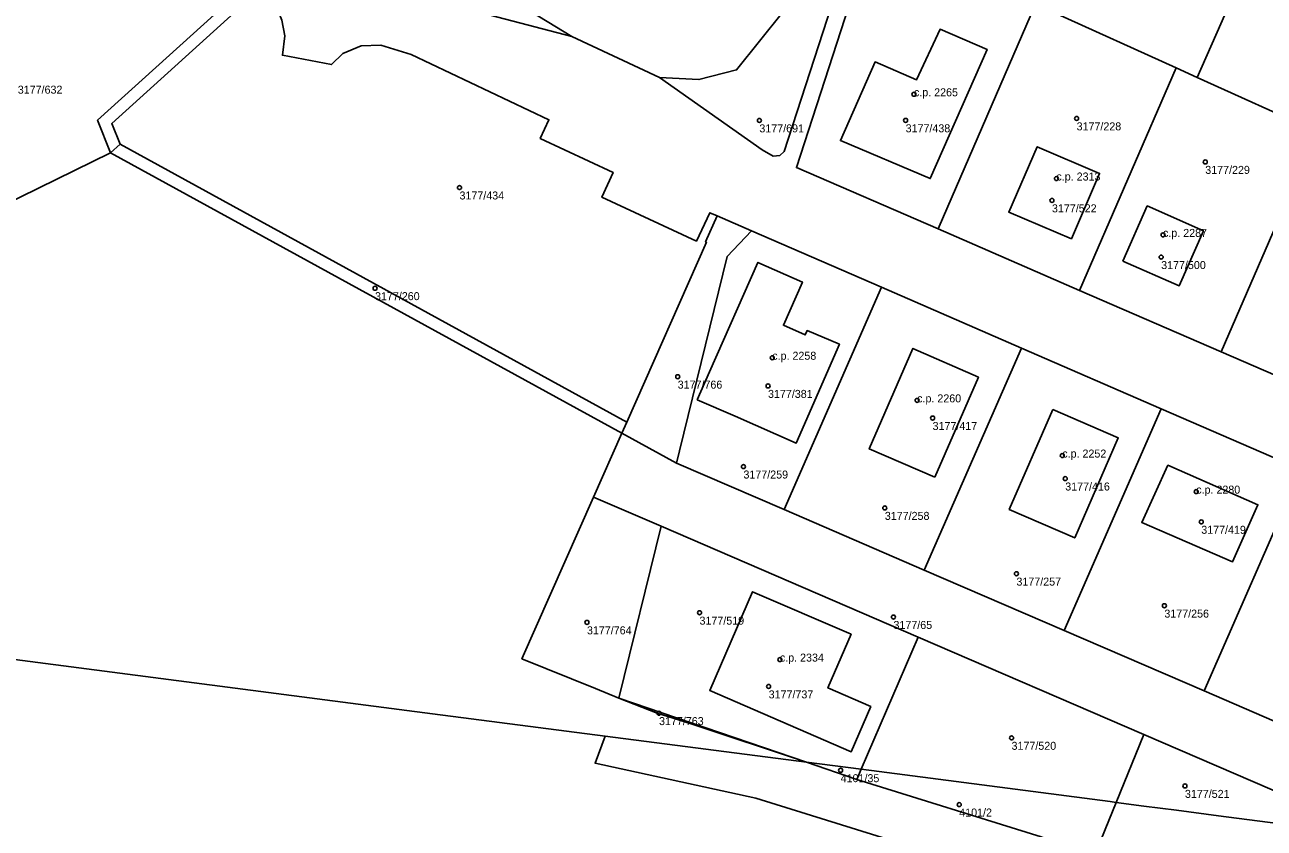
# Model space of a CAD drawing. Extents: x -878211 to -870363, y -1058464 to -1052522.
# Drawn here: x -874398.3 to -874243.4, y -1057039.9 to -1056939.4 of the extents above; entities that cross this region are included whole.
import ezdxf

# ---------------------------------------------------------------- set-up
doc = ezdxf.new("R2010")
doc.units = 0
for name, color, linetype in [('Vrstva 50', 7, 'Continuous'), ('Vrstva 51', 7, 'Continuous'), ('Vrstva 52', 7, 'Continuous')]:
    doc.layers.add(name, color=color, linetype=linetype)

msp = doc.modelspace()

# ---------------------------------------------------------------- linework, layer by layer
at = {"layer": 'Vrstva 50'}
for centre in [(-874287.13, -1056948.10994), (-874306.45, -1056951.37994), (-874288.17, -1056951.36994), (-874266.8, -1056951.12994), (-874250.72, -1056956.56994), (-874269.32, -1056958.63994), (-874343.93, -1056959.76994), (-874269.88, -1056961.37994), (-874256, -1056965.68994), (-874256.23, -1056968.46994), (-874354.49, -1056972.35994), (-874304.84, -1056981.04994), (-874316.66, -1056983.41994), (-874305.37, -1056984.57994), (-874286.73, -1056986.37994), (-874284.8, -1056988.58994), (-874268.59, -1056993.27994), (-874308.44, -1056994.65994), (-874268.22, -1056996.15994), (-874251.85, -1056997.78994), (-874290.77, -1056999.82994), (-874251.22, -1057001.56994), (-874274.32, -1057008.04994), (-874255.83, -1057012.04994), (-874313.93, -1057012.92994), (-874289.69, -1057013.46994), (-874328, -1057014.13994), (-874303.89, -1057018.78994), (-874305.29, -1057022.14994), (-874318.99, -1057025.48994), (-874274.93, -1057028.57994), (-874296.29, -1057032.62994), (-874253.26, -1057034.58994), (-874281.47, -1057036.91994)]:
    msp.add_circle(centre, 0.25, dxfattribs=at)
at = {"layer": 'Vrstva 51'}
for points in [[(-874324.96, -1056884.65), (-874320.96, -1056886.71), (-874320.59, -1056885.96), (-874317.31, -1056887.36), (-874315.74, -1056882.81), (-874317.2, -1056882.28), (-874322.56, -1056881.47), (-874325, -1056882.05), (-874327.32, -1056883.85), (-874328.98, -1056886.28), (-874331.81, -1056891.54), (-874351.14, -1056927.66), (-874351.9, -1056930.02), (-874352, -1056931.99), (-874351.54, -1056933.93), (-874344.73, -1056937.02), (-874329.9, -1056940.87), (-874340.09, -1056934.61), (-874342.8, -1056928.11), (-874342.12, -1056920.85), (-874331.98, -1056902.66), (-874326.54, -1056897.55), (-874323.49, -1056891.62), (-874327.49, -1056889.54)], [(-874323.68, -1056901.06), (-874326.54, -1056897.55), (-874331.98, -1056902.66), (-874342.12, -1056920.85), (-874342.8, -1056928.11), (-874340.09, -1056934.61), (-874329.9, -1056940.87), (-874318.93, -1056946), (-874314, -1056946.27), (-874309.3, -1056945.06), (-874300.68, -1056934.27), (-874293.26, -1056915.3), (-874296.22, -1056916.61), (-874298.98, -1056910.87)], [(-874254.36, -1056944.8), (-874251.74, -1056945.99), (-874239.29, -1056917.7), (-874257.28, -1056909.78), (-874269.65, -1056937.89)], [(-874303.34, -1056955.27), (-874289.89, -1056913.8), (-874293.26, -1056915.3), (-874300.68, -1056934.27), (-874309.3, -1056945.06), (-874314, -1056946.27), (-874318.93, -1056946), (-874306.08, -1056955.04), (-874304.71, -1056955.83), (-874303.88, -1056955.75)], [(-874233.82, -1056954.08), (-874230.38, -1056946.25), (-874221.3, -1056925.63), (-874239.29, -1056917.7), (-874251.74, -1056945.99), (-874236.77, -1056952.75)], [(-874284.12, -1056964.95), (-874271.94, -1056936.86), (-874292.24, -1056927.69), (-874301.81, -1056957.27)], [(-874313.17, -1056966.56), (-874311.71, -1056963.32), (-874312.65, -1056962.91), (-874314.32, -1056966.47), (-874326.13, -1056960.99), (-874324.73, -1056957.88), (-874333.84, -1056953.63), (-874332.76, -1056951.29), (-874349.96, -1056943.12), (-874353.75, -1056941.96), (-874356.23, -1056942.05), (-874358.53, -1056943), (-874359.94, -1056944.39), (-874366.06, -1056943.23), (-874365.75, -1056940.81), (-874366.12, -1056938.84), (-874366.89, -1056937), (-874363.23, -1056929.78), (-874365.89, -1056929.74), (-874370.3, -1056936.26), (-874387.39, -1056951.76), (-874386.36, -1056954.36), (-874323.02, -1056989.09), (-874313.07, -1056966.61)], [(-874371.61, -1056935.43), (-874378.02, -1056933.56), (-874384.62, -1056932.62), (-874418.48, -1056931.4), (-874418.48, -1056965.39), (-874407.88, -1056965.39), (-874387.56, -1056955.42), (-874389.17, -1056951.35)], [(-874254.36, -1056944.8), (-874269.65, -1056937.89), (-874271.94, -1056936.86), (-874284.12, -1056964.95), (-874266.42, -1056972.63)], [(-874277.98, -1056942.49), (-874283.86, -1056939.98), (-874286.8, -1056946.3), (-874291.99, -1056944.06), (-874296.33, -1056953.9), (-874285.09, -1056958.65)], [(-874277.98, -1056942.49), (-874285.09, -1056958.65), (-874296.33, -1056953.9), (-874291.99, -1056944.06), (-874286.8, -1056946.3), (-874283.86, -1056939.98)], [(-874254.36, -1056944.8), (-874266.42, -1056972.63), (-874248.73, -1056980.31), (-874236.77, -1056952.75), (-874251.74, -1056945.99)], [(-874230.04, -1056955.79), (-874233.82, -1056954.08), (-874236.77, -1056952.75), (-874248.73, -1056980.31), (-874231.03, -1056987.99), (-874219.19, -1056960.69)], [(-874386.36, -1056954.36), (-874387.56, -1056955.42), (-874323.63, -1056990.47), (-874323.02, -1056989.09)], [(-874263.92, -1056958.01), (-874267.45, -1056966.18), (-874275.28, -1056962.83), (-874271.71, -1056954.67)], [(-874263.92, -1056958.01), (-874271.71, -1056954.67), (-874275.28, -1056962.83), (-874267.45, -1056966.18)], [(-874261.02, -1056968.96), (-874253.99, -1056972.06), (-874250.95, -1056965.16), (-874257.98, -1056962.06)], [(-874261.02, -1056968.96), (-874257.98, -1056962.06), (-874250.95, -1056965.16), (-874253.99, -1056972.06)], [(-874307.45, -1056965.17), (-874311.71, -1056963.32), (-874313.17, -1056966.56), (-874313.07, -1056966.61), (-874323.02, -1056989.09), (-874323.63, -1056990.47), (-874316.81, -1056994.21), (-874316.44, -1056992.7), (-874310.47, -1056968.39)], [(-874316.44, -1056992.7), (-874316.81, -1056994.21), (-874303.34, -1057000.03), (-874291.17, -1056972.24), (-874307.45, -1056965.17), (-874310.47, -1056968.39)], [(-874314.22, -1056986.3), (-874309.48, -1056988.37), (-874301.87, -1056991.73), (-874296.44, -1056979.37), (-874300.48, -1056977.65), (-874300.72, -1056978.19), (-874303.44, -1056976.99), (-874301.06, -1056971.58), (-874306.64, -1056969.13), (-874312.69, -1056982.81)], [(-874314.22, -1056986.3), (-874312.69, -1056982.81), (-874306.64, -1056969.13), (-874301.06, -1056971.58), (-874303.44, -1056976.99), (-874300.72, -1056978.19), (-874300.48, -1056977.65), (-874296.44, -1056979.37), (-874301.87, -1056991.73), (-874309.48, -1056988.37)], [(-874273.69, -1056979.83), (-874291.17, -1056972.24), (-874303.34, -1057000.03), (-874285.84, -1057007.59)], [(-874284.5, -1056995.99), (-874292.71, -1056992.45), (-874287.25, -1056979.89), (-874279.07, -1056983.48)], [(-874284.5, -1056995.99), (-874279.07, -1056983.48), (-874287.25, -1056979.89), (-874292.71, -1056992.45)], [(-874285.84, -1057007.59), (-874268.34, -1057015.15), (-874256.21, -1056987.42), (-874273.69, -1056979.83)], [(-874269.76, -1056987.5), (-874261.59, -1056991.08), (-874267.04, -1057003.58), (-874275.21, -1057000.02)], [(-874269.76, -1056987.5), (-874275.21, -1057000.02), (-874267.04, -1057003.58), (-874261.59, -1056991.08)], [(-874268.34, -1057015.15), (-874250.85, -1057022.71), (-874238.72, -1056995.01), (-874256.21, -1056987.42)], [(-874323.63, -1056990.47), (-874327.17, -1056998.46), (-874318.73, -1057002.1), (-874286.59, -1057015.98), (-874258.4, -1057028.16), (-874228.74, -1057040.96), (-874199.95, -1057044.7), (-874208.32, -1057041.08), (-874215.85, -1057037.83), (-874233.35, -1057030.27), (-874250.85, -1057022.71), (-874268.34, -1057015.15), (-874285.84, -1057007.59), (-874303.34, -1057000.03), (-874316.81, -1056994.21)], [(-874247.31, -1057006.55), (-874244.14, -1056999.43), (-874255.39, -1056994.5), (-874258.65, -1057001.66)], [(-874247.31, -1057006.55), (-874258.65, -1057001.66), (-874255.39, -1056994.5), (-874244.14, -1056999.43)], [(-874233.35, -1057030.27), (-874221.24, -1057002.6), (-874238.72, -1056995.01), (-874250.85, -1057022.71)], [(-874327.17, -1056998.46), (-874336.12, -1057018.69), (-874326.92, -1057022.4), (-874324.02, -1057023.61), (-874318.73, -1057002.1)], [(-874324.02, -1057023.61), (-874300.54, -1057031.62), (-874293.72, -1057032.51), (-874286.59, -1057015.98), (-874318.73, -1057002.1)], [(-874312.65, -1057022.64), (-874307.31, -1057010.31), (-874294.98, -1057015.63), (-874297.88, -1057022.33), (-874292.52, -1057024.67), (-874294.96, -1057030.32)], [(-874312.65, -1057022.64), (-874294.96, -1057030.32), (-874292.52, -1057024.67), (-874297.88, -1057022.33), (-874294.98, -1057015.63), (-874307.31, -1057010.31)], [(-874258.4, -1057028.16), (-874286.59, -1057015.98), (-874293.72, -1057032.51), (-874262.62, -1057036.55), (-874261.85, -1057036.65)], [(-874300.54, -1057031.62), (-874324.02, -1057023.61), (-874319.23, -1057025.49), (-874315.12, -1057026.77)], [(-874228.74, -1057040.96), (-874258.4, -1057028.16), (-874261.85, -1057036.65), (-874258.41, -1057037.1), (-874254.31, -1057037.63), (-874249.05, -1057038.32)], [(-874300.54, -1057031.62), (-874294.26, -1057033.77), (-874293.72, -1057032.51)], [(-874294.26, -1057033.77), (-874271.24, -1057040.97), (-874264.68, -1057043.63), (-874261.85, -1057036.65), (-874262.62, -1057036.55), (-874293.72, -1057032.51)], [(-874264.68, -1057043.63), (-874238.04, -1057054.77), (-874235.3, -1057056.13), (-874228.74, -1057040.96), (-874249.05, -1057038.32), (-874254.31, -1057037.63), (-874258.41, -1057037.1), (-874261.85, -1057036.65)]]:
    msp.add_lwpolyline(points, close=True, dxfattribs=at)
for points in [[(-874142.56, -1057026.39), (-874160.25, -1057018.71), (-874177.95, -1057011.03), (-874195.64, -1057003.35), (-874213.34, -1056995.67), (-874231.03, -1056987.99), (-874248.73, -1056980.31), (-874266.42, -1056972.63), (-874284.12, -1056964.95), (-874301.81, -1056957.27), (-874292.24, -1056927.69), (-874287.47, -1056913.16), (-874275.44, -1056901.79), (-874257.28, -1056909.78), (-874239.29, -1056917.7), (-874221.3, -1056925.63), (-874203.3, -1056933.53), (-874185.3, -1056941.45), (-874167.31, -1056949.37), (-874149.31, -1056957.28), (-874131.32, -1056965.2)], [(-874289.89, -1056913.8), (-874303.34, -1056955.27), (-874303.88, -1056955.75), (-874304.71, -1056955.83), (-874306.08, -1056955.04), (-874318.93, -1056946), (-874329.9, -1056940.87), (-874344.73, -1056937.02)], [(-874371.61, -1056935.43), (-874389.17, -1056951.35), (-874387.56, -1056955.42), (-874386.36, -1056954.36), (-874387.39, -1056951.76), (-874370.3, -1056936.26)], [(-874366.12, -1056938.84), (-874365.75, -1056940.81), (-874366.06, -1056943.23), (-874359.94, -1056944.39), (-874358.53, -1056943), (-874356.23, -1056942.05), (-874353.75, -1056941.96), (-874349.96, -1056943.12), (-874332.76, -1056951.29), (-874333.84, -1056953.63), (-874324.73, -1056957.88), (-874326.13, -1056960.99), (-874314.32, -1056966.47), (-874312.65, -1056962.91), (-874311.71, -1056963.32)], [(-874545.62, -1056999.77), (-874347.29, -1057025.55), (-874325.74, -1057028.35), (-874300.54, -1057031.62), (-874315.12, -1057026.77), (-874319.23, -1057025.49), (-874324.02, -1057023.61), (-874326.92, -1057022.4), (-874336.12, -1057018.69), (-874327.17, -1056998.46), (-874323.63, -1056990.47), (-874387.56, -1056955.42), (-874407.88, -1056965.39)], [(-874311.71, -1056963.32), (-874307.45, -1056965.17), (-874291.17, -1056972.24), (-874273.69, -1056979.83), (-874256.21, -1056987.42), (-874238.72, -1056995.01), (-874221.24, -1057002.6), (-874203.75, -1057010.19), (-874185.32, -1057018.19), (-874168.01, -1057025.7), (-874150.7, -1057033.22), (-874132.36, -1057041.19)], [(-874273.58, -1057046.51), (-874306.9, -1057036.12), (-874326.98, -1057031.74), (-874325.74, -1057028.35), (-874347.29, -1057025.55), (-874545.62, -1056999.77)], [(-874271.24, -1057040.97), (-874294.26, -1057033.77), (-874300.54, -1057031.62), (-874325.74, -1057028.35), (-874326.98, -1057031.74), (-874306.9, -1057036.12), (-874273.58, -1057046.51)]]:
    msp.add_lwpolyline(points, dxfattribs=at)
at = {"layer": 'Vrstva 52'}
for points in [[(-874291.99, -1056944.06), (-874296.33, -1056953.9), (-874285.09, -1056958.65), (-874277.98, -1056942.49), (-874283.86, -1056939.98), (-874286.8, -1056946.3)], [(-874275.28, -1056962.83), (-874267.45, -1056966.18), (-874263.92, -1056958.01), (-874271.71, -1056954.67)], [(-874261.02, -1056968.96), (-874253.99, -1056972.06), (-874250.95, -1056965.16), (-874257.98, -1056962.06)], [(-874314.22, -1056986.3), (-874309.48, -1056988.37), (-874301.87, -1056991.73), (-874296.44, -1056979.37), (-874300.48, -1056977.65), (-874300.72, -1056978.19), (-874303.44, -1056976.99), (-874301.06, -1056971.58), (-874306.64, -1056969.13), (-874312.69, -1056982.81)], [(-874284.5, -1056995.99), (-874279.07, -1056983.48), (-874287.25, -1056979.89), (-874292.71, -1056992.45)], [(-874269.76, -1056987.5), (-874275.21, -1057000.02), (-874267.04, -1057003.58), (-874261.59, -1056991.08)], [(-874258.65, -1057001.66), (-874247.31, -1057006.55), (-874244.14, -1056999.43), (-874255.39, -1056994.5)], [(-874307.31, -1057010.31), (-874312.65, -1057022.64), (-874294.96, -1057030.32), (-874292.52, -1057024.67), (-874297.88, -1057022.33), (-874294.98, -1057015.63)]]:
    msp.add_lwpolyline(points, close=True, dxfattribs=at)

# ---------------------------------------------------------------- texts
at = {"layer": 'Vrstva 50'}
for s, p in [('3177/632', (-874399.14, -1056948.029)), ('c.p. 2265', (-874287.13, -1056948.36)), ('3177/691', (-874306.45, -1056952.869)), ('3177/438', (-874288.17, -1056952.859)), ('3177/228', (-874266.8, -1056952.619)), ('3177/229', (-874250.72, -1056958.059)), ('c.p. 2313', (-874269.32, -1056958.889)), ('3177/434', (-874343.93, -1056961.259)), ('3177/522', (-874269.88, -1056962.869)), ('c.p. 2287', (-874256, -1056965.94)), ('3177/500', (-874256.23, -1056969.959)), ('3177/260', (-874354.49, -1056973.849)), ('c.p. 2258', (-874304.84, -1056981.3)), ('3177/766', (-874316.66, -1056984.909)), ('3177/381', (-874305.37, -1056986.069)), ('c.p. 2260', (-874286.73, -1056986.629)), ('3177/417', (-874284.8, -1056990.079)), ('c.p. 2252', (-874268.59, -1056993.53)), ('3177/259', (-874308.44, -1056996.149)), ('3177/416', (-874268.22, -1056997.649)), ('c.p. 2280', (-874251.85, -1056998.04)), ('3177/258', (-874290.77, -1057001.319)), ('3177/419', (-874251.22, -1057003.059)), ('3177/257', (-874274.32, -1057009.539)), ('3177/519', (-874313.93, -1057014.419)), ('3177/256', (-874255.83, -1057013.539)), ('3177/764', (-874328, -1057015.629)), ('3177/65', (-874289.69, -1057014.959)), ('c.p. 2334', (-874303.89, -1057019.04)), ('3177/737', (-874305.29, -1057023.639)), ('3177/763', (-874318.99, -1057026.979)), ('3177/520', (-874274.93, -1057030.069)), ('4101/35', (-874296.29, -1057034.119)), ('3177/521', (-874253.26, -1057036.079)), ('4101/2', (-874281.47, -1057038.409))]:
    msp.add_text(s, height=0.999996, dxfattribs=at).set_placement(p)

doc.saveas('drawing.dxf')
